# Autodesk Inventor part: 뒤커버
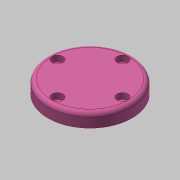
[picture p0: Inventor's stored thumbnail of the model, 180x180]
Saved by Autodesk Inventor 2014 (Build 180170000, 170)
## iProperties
Created: 2015-09
Part Number: 뒤커버
Material: 알루미늄 6061
Document SubType Name: Modeling
Designer: mduedu
Density: 1 g/cm^3
Appearance: Pink
Author: mduedu
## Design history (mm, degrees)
sketch "스케치1"
  geometry: L1 (0, 7.5)-(0, -7.5); L2 (0, 7.5)-(31, 7.5); L3 (31, 7.5)-(31, -2.5); L4 (31, -2.5)-(17.5, -2.5); L5 (17.5, -2.5)-(17.5, -7.5); L6 (17.5, -7.5)-(0, -7.5); 2 further points
  constraints: 12 end point, 2 parallel, 2 perpendicular, 1 coincident, 1 horizontal, 1 midpoint, 1 vertical
  dimensions: "d0" = 15 distance of L1.start L1.end; "d1" = 62 diameter of L3 L1; "d2" = 35 diameter of L5 L1; "d3" = 10 distance of L2.end L3.end
revolve "회전1" sketch "스케치1" stored, may be unused: angle "d4" = 90 deg
fillet "모깎기2" dims "d48" = 3
sketch "스케치4" dims "d49" = 48
  geometry: 3 further points
  constraints: 2 vertical alignment, 1 coincident, 2 other
hole "구멍4" sketch "스케치4" at (0, 24) diameter "d50" = 4.5; stored, may be unused: countersink angle "d54" = 90 deg, drill point angle "d56" = 118 deg; dims "d51" = 6, "d52" = 8, "d53" = 4.4, "d55" = 8
hole "구멍5" diameter "d62" = 24; stored, may be unused: countersink angle "d66" = 90 deg, drill point angle "d68" = 0 deg; dims "d60" = 10, "d61" = 10, "d63" = 6, "d64" = 4, "d65" = 2, "d67" = 8
fillet "모깎기3" dims "d69" = 3
chamfer "모따기3" distance "d43" = 1; stored, may be unused: second distance "d44" = 2, angle "d45" = 45 deg
node "솔리드1"
pattern_circular "원형 패턴1" dims angle "d58" = 360 deg
